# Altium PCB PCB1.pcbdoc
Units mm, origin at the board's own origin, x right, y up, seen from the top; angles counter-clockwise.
Board outline 202.56 x 70.18 mm, 2 copper layers (Top Layer, Bottom Layer); 24 components, 21 nets, 136 pads, 27 vias.
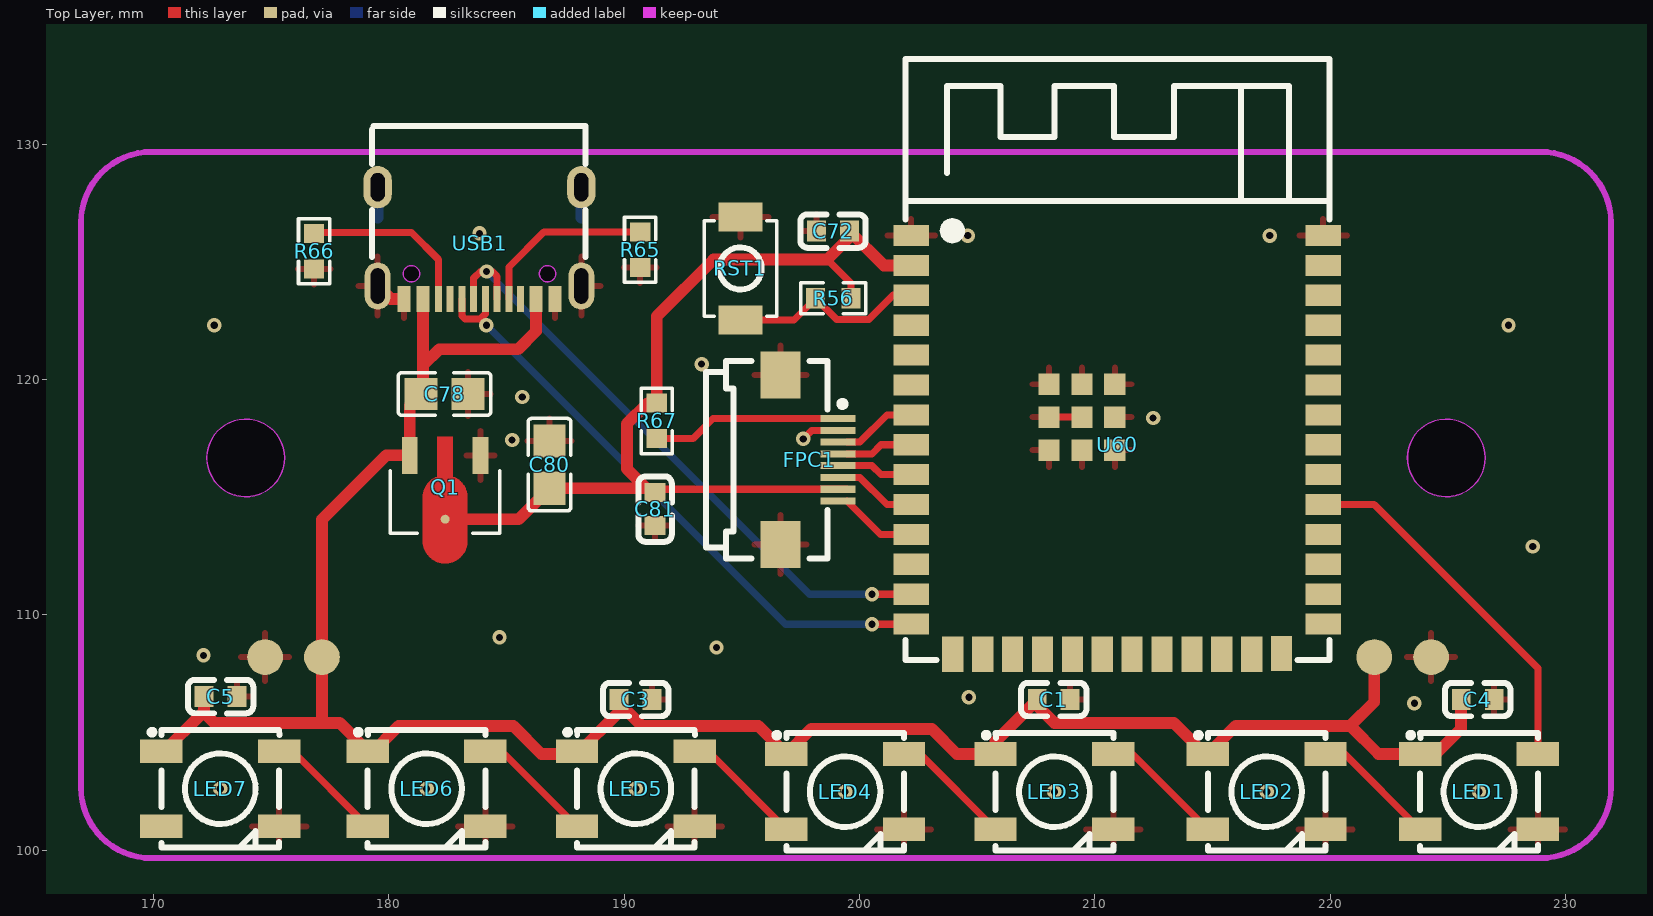
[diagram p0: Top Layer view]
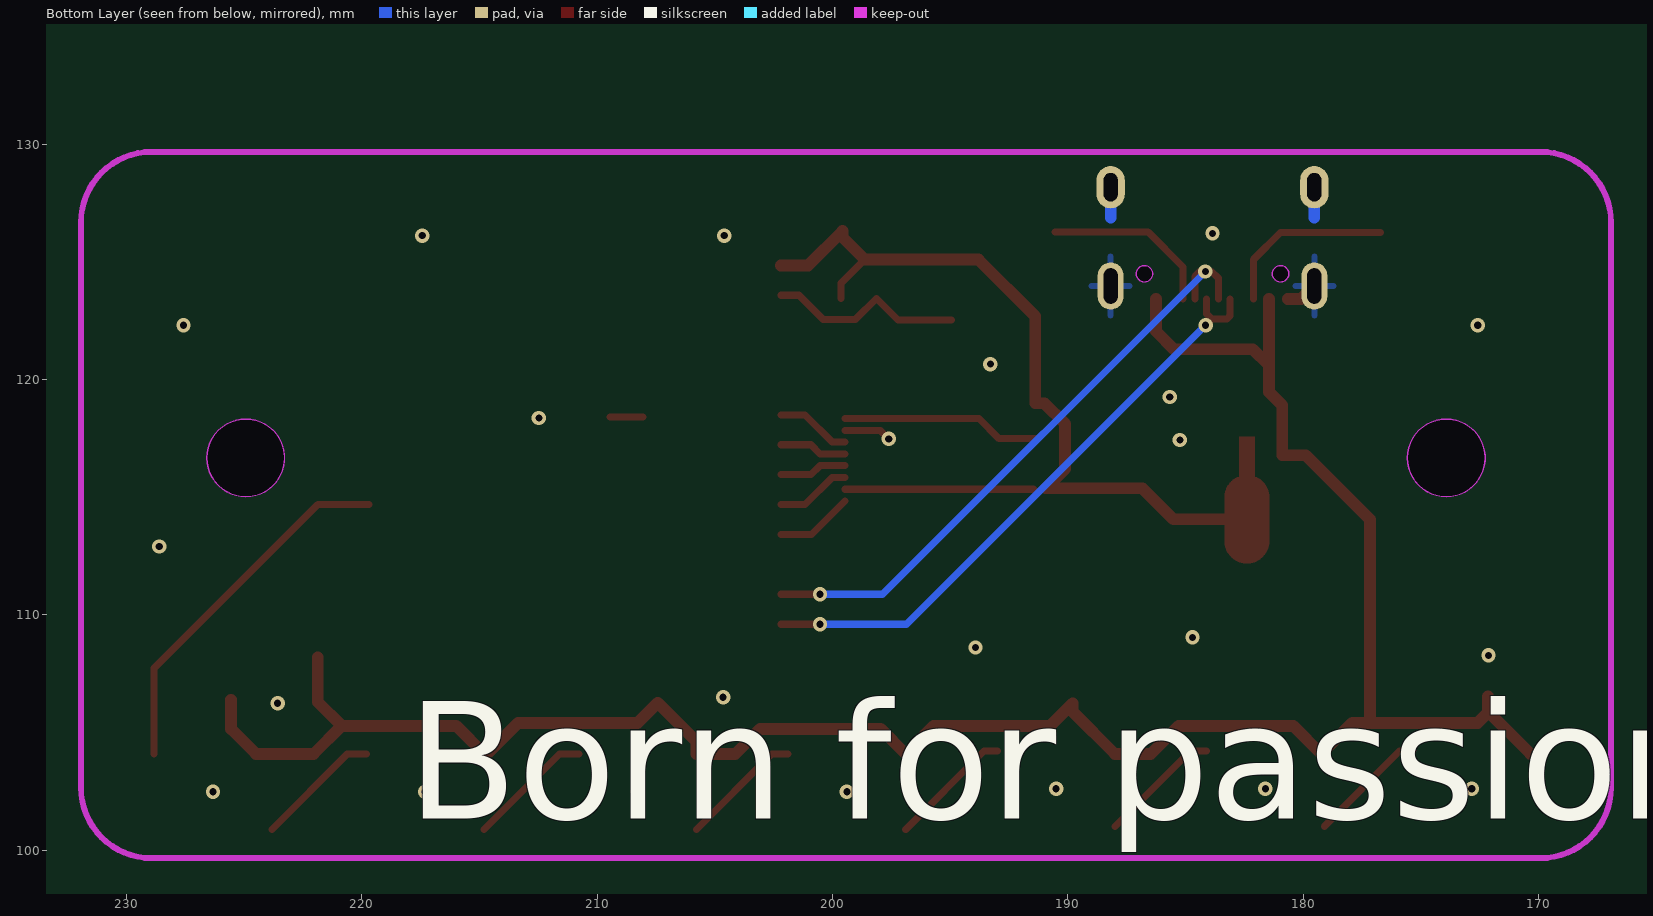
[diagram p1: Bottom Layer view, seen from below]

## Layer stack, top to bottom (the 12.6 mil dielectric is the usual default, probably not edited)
Top Layer: signal copper (thickness not stored)
Dielectric: dielectric 0.32, FR-4, Dk 4.8
Bottom Layer: signal copper (thickness not stored)

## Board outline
272.415,69.85 69.85,69.85 69.85,140.026 272.415,140.026
cut-out: 175.577,116.667 cw(c173.927,116.667) 172.277,116.667 cw(c173.927,116.667)
cut-out: 226.577,116.667 cw(c224.927,116.667) 223.277,116.667 cw(c224.927,116.667)

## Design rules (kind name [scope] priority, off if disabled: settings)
BoardOutlineClearance copperThickness1oz [All] p0: genericclearance=0.254 ignorepadtopadclearanceinfootprint=FALSE except(0: Arc-SplitContinuation Track-SplitContinuation SMDPad-SplitContinuation THPad-SplitContinuation Via-SplitContinuation Fill-SplitContinuation Poly-SplitContinuation Region-SplitContinuation Text-SplitContinuation; 0.152: Track-CutoutEdge SMDPad-CutoutEdge THPad-CutoutEdge Via-CutoutEdge Region-CutoutEdge; 0.3: Track-OutlineEdge SMDPad-OutlineEdge THPad-OutlineEdge Via-OutlineEdge Fill-OutlineEdge Region-OutlineEdge Poly-OutlineEdge Text-OutlineEdge Fill-CutoutEdge)
BoardOutlineClearance copperThickness2oz [All] p0: genericclearance=0.254 ignorepadtopadclearanceinfootprint=FALSE except(0: Arc-SplitContinuation Track-SplitContinuation SMDPad-SplitContinuation THPad-SplitContinuation Via-SplitContinuation Fill-SplitContinuation Poly-SplitContinuation Region-SplitContinuation Text-SplitContinuation; 0.152: Track-CutoutEdge SMDPad-CutoutEdge THPad-CutoutEdge Via-CutoutEdge Region-CutoutEdge; 0.3: Track-OutlineEdge SMDPad-OutlineEdge THPad-OutlineEdge Via-OutlineEdge Fill-OutlineEdge Region-OutlineEdge Poly-OutlineEdge Text-OutlineEdge Fill-CutoutEdge)
Clearance copperThickness1oz [(InNet('19') OR InNet('20') OR InNet('IN') OR InNet('3.3V') OR InNet('GND') OR InNet('5V') OR InNet('CS') OR InNet('DC') OR InNet('RES') OR InNet('SDA') OR InNet('SCL') OR InNet('$1N578') OR InNet('$1N763') OR InNet('$1N750') OR InNet('$1N948') OR InNet('$1N935') OR InNet('$1N1133') OR InNet('EN') OR InNet('$1N11166') OR InNet('$1N11313') OR InNet('$1N12509'))] p1: gap=0.178 ignorepadtopadclearanceinfootprint=FALSE except(0.102: Track-Track; 0.152: Track-SMDPad SMDPad-SMDPad Track-THPad SMDPad-THPad THPad-THPad Track-Via SMDPad-Via THPad-Via Via-Via SMDPad-Fill THPad-Fill Via-Fill Fill-Fill Track-Region SMDPad-Region THPad-Region Via-Region Region-Region Track-Poly SMDPad-Poly THPad-Poly Via-Poly Fill-Poly Region-Poly Poly-Poly Track-Text SMDPad-Text THPad-Text Via-Text Fill-Text Region-Text Poly-Text Text-Text; 0.175: Track-Hole SMDPad-Hole THPad-Hole Via-Hole Fill-Hole Region-Hole Poly-Hole Text-Hole Sheet-Hole; 0.3: Track-Fill Fill-Region Track-Sheet SMDPad-Sheet THPad-Sheet Via-Sheet Fill-Sheet Region-Sheet Poly-Sheet Text-Sheet)
Clearance copperThickness2oz [All] p1: gap=0.178 ignorepadtopadclearanceinfootprint=FALSE except(0.152: Track-SMDPad SMDPad-SMDPad Track-THPad SMDPad-THPad THPad-THPad Track-Via SMDPad-Via THPad-Via Via-Via SMDPad-Fill THPad-Fill Via-Fill Fill-Fill Track-Region SMDPad-Region THPad-Region Via-Region Region-Region Track-Poly SMDPad-Poly THPad-Poly Via-Poly Fill-Poly Region-Poly Poly-Poly Track-Text SMDPad-Text THPad-Text Via-Text Fill-Text Region-Text Poly-Text Text-Text; 0.175: Track-Hole SMDPad-Hole THPad-Hole Via-Hole Fill-Hole Region-Hole Poly-Hole Text-Hole Sheet-Hole; 0.203: Track-Track; 0.3: Track-Fill Fill-Region Track-Sheet SMDPad-Sheet THPad-Sheet Via-Sheet Fill-Sheet Region-Sheet Poly-Sheet Text-Sheet)
DiffPairsRouting differentialPair [All] p1: maxuncoupledlength=10 minlimit=6 maxlimit=6 mostfreqgap=6 toplayer_minwidth=5 toplayer_prefwidth=10 toplayer_maxwidth=100 bottomlayer_minwidth=5 bottomlayer_prefwidth=10 bottomlayer_maxwidth=100
PasteMaskExpansion pasteMaskExpansion [All] p1: expansion=0
PlaneConnect innerPlane [All] p1: planeconnectstyle=Relief reliefexpansion=0.508 reliefentries=4 reliefconductorwidth=0.254 reliefairgap=0.254
PolygonConnect copperRegion [All] p1: connectstyle=Relief reliefentries=4 reliefconductorwidth=10 polygonreliefangle="90 Angle" airgapwidth=10
RoutingVias viaSize [All] p1: viastyle="Through Hole" holewidth=12.0078 minholewidth=11.811 maxholewidth=248.0314 width=24.0158 minwidth=19.685 maxwidth=393.7008
SolderMaskExpansion solderMaskExpansion [All] p1: useseparateexpansions=TRUE expansion=2 expansionbottom=2
Width copperThickness1oz [All] p1: maxlimit=100 minlimit=5 preferedwidth=10
Width copperThickness2oz [All] p1: maxlimit=100 minlimit=8 preferedwidth=10

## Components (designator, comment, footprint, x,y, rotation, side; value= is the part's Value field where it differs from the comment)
C1 "100nF" C0603 208.249,106.403 r0 top
C3 "100nF" C0603 190.491,106.403 r0 top
C4 "100nF" C0603 226.261,106.403 r0 top
C5 "100nF" C0603 172.86,106.53 r0 top
C72 "100nF" C0603 198.875,126.304 r180 top
C78 "1uF" C0805 182.372,119.38 r180 top
C80 "1uF" C0805 186.833,116.38 r90 top
C81 "100nF" C0603 191.317,114.494 r270 top
FPC1 "FC-05A8P11H20" FPC-SMD_8P-P0.50_FC05-S08FCT-00 197.866,116.586 r270 top
LED1 "WS2812B-V5/W" LED-SMD_4P-L5.0-W5.0-TL-1 226.314,102.489 r0 top
LED2 "WS2812B-V5/W" LED-SMD_4P-L5.0-W5.0-TL-1 217.297,102.489 r0 top
LED3 "WS2812B-V5/W" LED-SMD_4P-L5.0-W5.0-TL-1 208.28,102.489 r0 top
LED4 "WS2812B-V5/W" LED-SMD_4P-L5.0-W5.0-TL-1 199.39,102.489 r0 top
LED5 "WS2812B-V5/W" LED-SMD_4P-L5.0-W5.0-TL-1 190.5,102.616 r0 top
LED6 "WS2812B-V5/W" LED-SMD_4P-L5.0-W5.0-TL-1 181.61,102.616 r0 top
LED7 "WS2812B-V5/W" LED-SMD_4P-L5.0-W5.0-TL-1 172.847,102.616 r0 top
Q1 "AMS1117-3.3V" SOT-89-3_L4.5-W2.5-P1.50-LS4.2-BR 182.398,115.42 r90 top
R56 "10kΩ" R0603 198.882,123.444 r0 top
R65 "5.1k" R0603 190.68,125.512 r90 top
R66 "5.1k" R0603 176.831,125.443 r90 top
R67 "10Ω" R0603 191.389,118.237 r90 top
RST1 "TS-1088-AR02016" SW-SMD_L3.9-W3.0-P4.45 194.945,124.714 r270 top
U60 "2.4GHz" WIRELM-SMD_ESP32-S3-WROOM-1 210.947,117.221 r0 top
USB1 "TYPE-C 16PIN 2MD(073)" USB-C-SMD_TYPE-C-16PIN-2MD-073 183.859,125.794 r180 top

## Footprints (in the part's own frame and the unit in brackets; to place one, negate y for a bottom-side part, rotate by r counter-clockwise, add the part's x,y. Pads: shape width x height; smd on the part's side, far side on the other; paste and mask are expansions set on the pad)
C0603 [mm]
  rect 0.8x0.9 smd: 1(-0.7,0) 2(0.7,0)
  silkscreen extent -1.39,-0.71 1.39,0.71
C0805 [mm]
  rect 1.41x1.35 smd: 1(-1,0) 2(1,0)
  silkscreen extent -1.96,-0.9 1.96,0.9
FPC-SMD_8P-P0.50_FC05-S08FCT-00 [mm]
  rect 0.3x1.5 smd: 1(-1.75,1.225) 2(-1.25,1.225) 3(-0.75,1.225) 4(-0.25,1.225) 5(0.25,1.225) 6(0.75,1.225) 7(1.25,1.225) 8(1.751,1.225)
  rect 2x1.7 smd: 9(3.6,-1.225) 10(-3.6,-1.225)
  silkscreen extent -4.2,-4.38 4.2,1.54
LED-SMD_4P-L5.0-W5.0-TL-1 [mm]
  rect 1.8x1 smd: 1(-2.5,1.6) 2(-2.5,-1.6) 3(2.5,-1.6) 4(2.5,1.6)
  silkscreen extent -3,-2.5 2.51,2.5
R0603 [mm]
  rect 0.806x0.864 smd: 1(-0.753,0) 2(0.753,0)
  silkscreen extent -1.39,-0.66 1.39,0.66
SOT-89-3_L4.5-W2.5-P1.50-LS4.2-BR [mm]
  rect 1.575x0.672 smd: 1(1.356,-1.5) 3(1.356,1.5)
  round 0.38 smd: 2(-1.356,0)
  Top Layer region: -2.283,0.95 -0.429,0.95 -0.384,0.949 -0.34,0.946 -0.296,0.94 -0.252,0.933 -0.208,0.924 -0.165,0.912 -0.123,0.899 -0.081,0.884 -0.04,0.866 0,0.847 0.04,0.826 0.078,0.803 0.115,0.779 0.151,0.752 0.185,0.724 0.219,0.695 0.251,0.664 0.281,0.631 0.31,0.597 0.337,0.562 0.362,0.525 0.386,0.488 0.408,0.449 0.428,0.409 0.447,0.33 2.144,0.33 2.144,-0.33 0.447,-0.33 0.428,-0.409 0.408,-0.449 0.386,-0.488 0.362,-0.526 0.337,-0.562 0.31,-0.597 0.281,-0.631 0.251,-0.664 0.219,-0.695 0.185,-0.725 0.151,-0.753 0.115,-0.779 0.078,-0.804 0.04,-0.827 0,-0.848 -0.04,-0.867 -0.081,-0.884 -0.123,-0.899 -0.165,-0.913 -0.208,-0.924 -0.252,-0.934 -0.296,-0.941 -0.34,-0.946 -0.384,-0.949 -0.429,-0.95 -2.283,-0.95 -2.328,-0.949 -2.372,-0.946 -2.416,-0.941 -2.46,-0.934 -2.504,-0.924 -2.547,-0.913 -2.589,-0.899 -2.631,-0.884 -2.672,-0.867 -2.713,-0.848 -2.752,-0.827 -2.79,-0.804 -2.827,-0.779 -2.863,-0.753 -2.898,-0.725 -2.931,-0.695 -2.963,-0.664 -2.993,-0.631 -3.022,-0.597 -3.049,-0.562 -3.075,-0.526 -3.098,-0.488 -3.12,-0.449 -3.141,-0.409 -3.159,-0.369 -3.175,-0.327 -3.189,-0.285 -3.202,-0.242 -3.212,-0.199 -3.22,-0.155 -3.227,-0.111 -3.231,-0.067 -3.233,-0.022 -3.233,0.022 -3.231,0.067 -3.227,0.111 -3.22,0.155 -3.212,0.199 -3.202,0.242 -3.189,0.285 -3.175,0.327 -3.159,0.369 -3.141,0.409 -3.12,0.449 -3.098,0.488 -3.075,0.525 -3.049,0.562 -3.022,0.597 -2.993,0.631 -2.963,0.664 -2.931,0.695 -2.898,0.724 -2.863,0.752 -2.827,0.779 -2.79,0.803 -2.752,0.826 -2.713,0.847 -2.672,0.866 -2.631,0.884 -2.589,0.899 -2.547,0.912 -2.504,0.924 -2.46,0.933 -2.416,0.94 -2.372,0.946 -2.328,0.949
  silkscreen extent -1.95,-2.33 0.7,2.33
SW-SMD_L3.9-W3.0-P4.45 [mm]
  rect 1.23x1.86 smd: 1(-2.185,0) 2(2.185,0)
  silkscreen extent -2.03,-1.54 2.03,1.54
USB-C-SMD_TYPE-C-16PIN-2MD-073 [mm]
  oval 1.2x1.8 hole 0.6 slot 1.2 at 90 deg: 13(-4.325,-2.375) 14(4.325,-2.375)
  oval 1.1x2 hole 0.6 slot 1.5 at 90 deg: 13(-4.325,1.825) 14(4.325,1.825)
  rect 0.55x1.1 smd: A1B12(-3.2,2.375) A4B9(-2.4,2.375) B1A12(3.2,2.375) B4A9(2.4,2.375)
  rect 0.3x1.1 smd: A5(-1.25,2.375) A6(-0.25,2.375) A7(0.25,2.375) A8(1.25,2.375) B5(1.75,2.375) B6(0.75,2.375) B7(-0.75,2.375) B8(-1.75,2.375)
  Board Outline Layer circle w0.005: c-2.89,1.305 r0.35
  Board Outline Layer circle w0.005: c2.89,1.305 r0.35
  Board Outline Layer region: -3.24,1.305 -3.205,1.457 -3.108,1.579 -2.968,1.646 -2.812,1.646 -2.672,1.579 -2.575,1.457 -2.54,1.305 -2.54,1.305 -2.575,1.153 -2.672,1.031 -2.812,0.964 -2.968,0.964 -3.108,1.031 -3.205,1.153 -3.24,1.305
  Board Outline Layer region: 2.54,1.305 2.575,1.457 2.672,1.579 2.812,1.646 2.968,1.646 3.108,1.579 3.205,1.457 3.24,1.305 3.24,1.305 3.205,1.153 3.108,1.031 2.968,0.964 2.812,0.964 2.672,1.031 2.575,1.153 2.54,1.305
  Multi-Layer board cut-out: -3.24,1.305 -3.205,1.457 -3.108,1.579 -2.968,1.646 -2.812,1.646 -2.672,1.579 -2.575,1.457 -2.54,1.305 -2.54,1.305 -2.575,1.153 -2.672,1.031 -2.812,0.964 -2.968,0.964 -3.108,1.031 -3.205,1.153 -3.24,1.305
  Multi-Layer board cut-out: 2.54,1.305 2.575,1.457 2.672,1.579 2.812,1.646 2.968,1.646 3.108,1.579 3.205,1.457 3.24,1.305 3.24,1.305 3.205,1.153 3.108,1.031 2.968,0.964 2.812,0.964 2.672,1.031 2.575,1.153 2.54,1.305
  silkscreen extent -4.5,-4.97 4.57,0.6
WIRELM-SMD_ESP32-S3-WROOM-1 [mm]
  rect 1.5x0.9 smd: 1(-8.75,8.895) 2(-8.75,7.625) 3(-8.75,6.355) 4(-8.75,5.085) 5(-8.75,3.815) 6(-8.75,2.545) 7(-8.75,1.275) 8(-8.75,0.005) 9(-8.75,-1.265) 10(-8.75,-2.535) 11(-8.75,-3.805) 12(-8.75,-5.075) 13(-8.75,-6.345) 14(-8.75,-7.615) 27(8.75,-7.615) 28(8.75,-6.345) 29(8.75,-5.075) 30(8.75,-3.805) 31(8.75,-2.535) 32(8.75,-1.265) 33(8.75,0.005) 34(8.75,1.275) 35(8.75,2.545) 36(8.75,3.815) 37(8.75,5.085) 38(8.75,6.355) 39(8.75,7.625) 40(8.75,8.895)
  rect 0.9x1.5 smd: 15(-6.985,-8.895) 16(-5.715,-8.895) 17(-4.445,-8.895) 18(-3.175,-8.895) 19(-1.905,-8.895) 20(-0.635,-8.895) 21(0.635,-8.895) 22(1.905,-8.895) 23(3.175,-8.895) 24(4.445,-8.895) 25(5.715,-8.895) 26(6.985,-8.865)
  rect 0.9x0.9 smd: 41(-2.9,-0.225) 41(-2.9,1.175) 41(-2.9,2.575) 41(-1.5,-0.225) 41(-1.5,1.175) 41(-1.5,2.575) 41(-0.1,-0.225) 41(-0.1,1.175) 41(-0.1,2.575)
  silkscreen extent -9,-9.14 9.02,16.39

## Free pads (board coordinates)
  round 1.524 smd: 1(174.752,108.204) 1(224.282,108.204) 2(177.165,108.204) 2(221.869,108.204)

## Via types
v1: diameter 0.61, hole 0.305, Top Layer to Bottom Layer, 27 vias

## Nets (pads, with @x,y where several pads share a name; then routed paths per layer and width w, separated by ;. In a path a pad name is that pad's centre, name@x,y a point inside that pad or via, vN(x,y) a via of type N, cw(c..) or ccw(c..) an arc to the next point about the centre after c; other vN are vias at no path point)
3.3V: C72.1 C80.1 C81.1 FPC1.7 Q1.2 R56.2 R67.2 U60.2 | length 40.8
  Top Layer w0.3: C81.1 191.459,115.336 FPC1.7@199.472,115.336 ; 198.628,125.095 199.635,124.088 R56.2
  Top Layer w0.5: Q1.2 185.517,114.064 C80.1 190.944,115.38 190.119,116.205 190.119,118.11 190.999,118.99 R67.2 191.389,122.682 193.802,125.095 198.628,125.095 199.575,126.042 C72.1 201.033,124.846 U60.2
5V: C1.1 C3.1 C4.1 C5.1 C78.2 LED1.1 LED2.1 LED3.1 LED4.1 LED5.1 LED6.1 LED7.1 pad.2 Q1.3 USB1.A4B9 USB1.B4A9 | length 96.5
  Top Layer w0.5: LED7.1@170.347,104.089 172.16,105.902 ; C5.1 172.16,105.902 ; USB1.B4A9 181.459,120.599 ; USB1.A4B9 186.259,122.047 185.497,121.285 182.145,121.285 181.459,120.599 ; pad.2@221.869,108.204 221.869,106.299 220.853,105.283 ; C4.1@225.552,106.394 225.552,105.156 224.485,104.089 LED1.1 222.047,104.089 220.853,105.283 ; 172.16,105.902 172.16,105.843 172.593,105.41 177.165,105.41 ; 177.165,105.41 177.165,108.204 177.165,114.046 179.895,116.776 Q1.3 180.898,118.906 C78.2 181.459,119.467 181.459,120.599 ; 177.165,105.41 177.916,105.41 179.237,104.089 180.431,105.283 185.293,105.283 186.487,104.089 188,104.089 189.791,105.88 189.791,106.246 190.754,105.283 195.696,105.283 LED4.1 197.957,105.156 203.073,105.156 204.14,104.089 LED3.1 205.78,104.626 207.422,106.268 208.28,105.41 213.349,105.41 214.67,104.089 LED2.1 215.991,105.283 220.853,105.283
19: U60.13 USB1.A7 USB1.B7 | length 26.8
  Top Layer w0.3: USB1.A7 183.609,124.3 183.896,124.587 184.404,124.587 184.609,124.382 USB1.B7 ; v1(200.533,110.876) U60.13
  Bottom Layer w0.3: v1(184.16,124.587) 197.871,110.876 v1(200.533,110.876)
20: U60.14 USB1.A6 USB1.B6 | length 26.2
  Top Layer w0.3: USB1.B6 183.109,122.707 183.249,122.567 183.884,122.567 ; USB1.A6 184.109,122.792 183.884,122.567 ; v1(184.15,122.301) 183.884,122.567 ; v1(200.533,109.601) 202.192,109.601 U60.14
  Bottom Layer w0.3: v1(184.15,122.301) 196.85,109.601 v1(200.533,109.601)
$1N578: LED1.2 LED2.4 | length 5.3
  Top Layer w0.3: LED2.4 220.614,104.089 LED1.2
$1N750: LED3.2 LED4.4 | length 5.2
  Top Layer w0.3: LED4.4 202.58,104.089 LED3.2
$1N763: LED2.2 LED3.4 | length 5.3
  Top Layer w0.3: LED3.4 211.597,104.089 LED2.2
$1N935: LED5.2 LED6.4 | length 5.2
  Top Layer w0.3: LED6.4 184.8,104.216 LED5.2
$1N948: LED4.2 LED5.4 | length 5.3
  Top Layer w0.3: LED5.4 193.563,104.216 LED4.2
$1N1133: LED6.2 LED7.4 | length 5.1
  Top Layer w0.3: LED7.4 175.91,104.216 LED6.2
$1N11166: R65.2 USB1.A5 | length 7.4
  Top Layer w0.3: USB1.A5 185.109,124.784 186.59,126.265 R65.2@190.553,126.265
$1N11313: R66.2 USB1.B5 | length 7.5
  Top Layer w0.3: R66.2@176.728,126.238 180.975,126.238 182.109,125.104 USB1.B5
$1N12509: FPC1.1 R67.1 | length 8.4
  Top Layer w0.3: R67.1 192.922,117.484 193.774,118.336 FPC1.1@199.472,118.336
CS: FPC1.8 U60.11 | length 3.3
  Top Layer w0.3: FPC1.8@199.472,114.835 200.892,113.416 U60.11
DC: FPC1.4 U60.8 | length 2.9
  Top Layer w0.3: FPC1.4@199.472,116.836 200.529,116.836 200.919,117.226 U60.8
EN: R56.1 RST1.2 U60.3 | length 8.4
  Top Layer w0.3: RST1.2 197.214,122.529 R56.1 199.018,122.555 200.406,122.555 201.427,123.576 U60.3
GND: C1.2 C3.2 C4.2 C5.2 C72.2 C78.1 C80.2 C81.2 FPC1.2 FPC1.9 FPC1.10 LED1.3 LED2.3 LED3.3 LED4.3 LED5.3 LED6.3 LED7.3 pad.1 Q1.1 R65.1 R66.1 RST1.1 U60.1 U60.40 U60.41 USB1.13 USB1.14 USB1.A1B12 USB1.B1A12 | length 7.4
  Top Layer w0.3: v1(197.612,117.475) 197.973,117.836 FPC1.2@199.472,117.836 ; U60.41@208.047,118.396 U60.41@209.447,118.396
  Top Layer w0.5: USB1.14@179.534,123.969 180.084,123.419 USB1.B1A12
  Bottom Layer w0.5: 179.534,126.873 USB1.14@179.534,128.169 ; 188.184,126.873 USB1.13@188.184,128.169
  other v1: 199.391,102.489 208.281,102.489 217.298,102.489 226.315,102.489 172.848,102.616 181.611,102.616 190.501,102.616 223.571,106.248 204.648,106.502 172.136,108.28 193.924,108.615 184.709,109.042 228.6,112.903 185.245,117.427 212.471,118.364 185.674,119.253 193.294,120.65 172.593,122.301 227.57,122.301 204.597,126.111 217.424,126.111 183.859,126.204
IN: LED1.4 U60.31 | length 15.6
  Top Layer w0.3: U60.31 221.864,114.686 228.814,107.736 LED1.4
RES: FPC1.3 U60.7 | length 3.2
  Top Layer w0.3: FPC1.3@199.472,117.336 200.013,117.336 201.173,118.496 U60.7
SCL: FPC1.6 U60.10 | length 3.2
  Top Layer w0.3: FPC1.6@199.472,115.836 200.013,115.836 201.163,114.686 U60.10
SDA: FPC1.5 U60.9 | length 2.9
  Top Layer w0.3: FPC1.5@199.472,116.336 200.529,116.336 200.909,115.956 U60.9
pads on no net: LED7.2 U60.4 U60.5 U60.6 U60.12 U60.15 U60.16 U60.17 U60.18 U60.19 U60.20 U60.21 U60.22 U60.23 U60.24 U60.25 U60.26 U60.27 U60.28 U60.29 U60.30 U60.32 U60.33 U60.34 U60.35 U60.36 U60.37 U60.38 U60.39 USB1.A8 USB1.B8

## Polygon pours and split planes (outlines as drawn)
GND on Top Layer (solid, remove dead copper, pour order 0): 76.2,127.381 266.065,127.381 266.065,76.2 76.2,76.2
GND on Bottom Layer (solid, remove dead copper, pour order 2): 157.988,127.381 239.776,127.381 239.776,92.202 157.988,92.202

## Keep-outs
Board Outline Layer:
  circle w0.025: c173.927,116.667 r1.65
  region: 175.577,116.667 cw(c173.927,116.667) 172.277,116.667 cw(c173.927,116.667)
  circle w0.025: c224.927,116.667 r1.65
  region: 226.577,116.667 cw(c224.927,116.667) 223.277,116.667 cw(c224.927,116.667)
  lines w0.254: 166.927,102.667 ccw(c169.927,102.667) 169.927,99.667 228.927,99.667 ccw(c228.927,102.667) 231.927,102.667 231.927,126.667 ccw(c228.927,126.667) 228.927,129.667 169.927,129.667 ccw(c169.927,126.667) 166.927,126.667 166.927,102.667

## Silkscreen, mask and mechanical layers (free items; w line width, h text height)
Bottom Silkscreen Layer:
  text "Born for passion" at 218.059,101.346 h5
Mechanical Layer:
  circle w0.025: c173.927,116.667 r1.65
  circle w0.025: c224.927,116.667 r1.65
